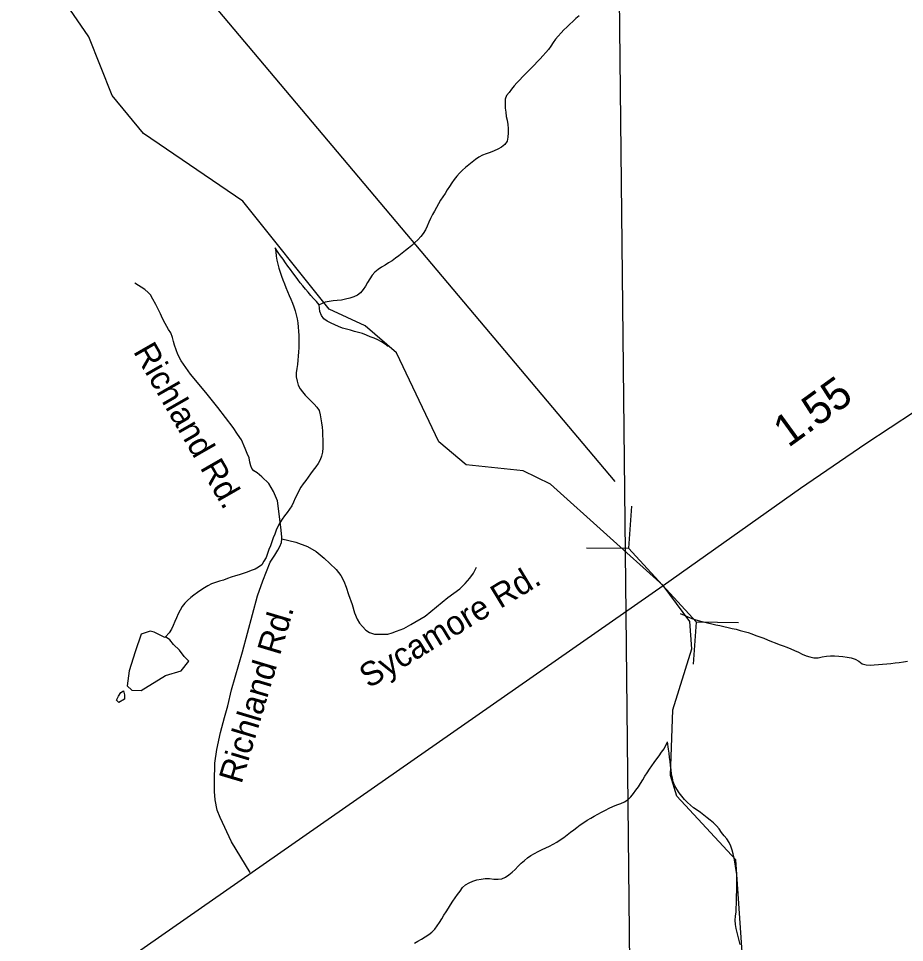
# Model space of a CAD drawing. Extents: x 1950930 to 2061844, y 904556 to 1017002.
# Drawn here: x 1978977 to 1982478, y 957687 to 961340 of the extents above; entities that cross this region are included whole.
import ezdxf

# ---------------------------------------------------------------- set-up
doc = ezdxf.new("R2010")
doc.units = 0
for name, color, linetype in [('Exist Hydrographic Creek Single Shore', 7, 'Continuous'), ('Exist Hydrographic Creek Single Shore Label', 7, 'Continuous'), ('Exist Hydrographic Misc Water Feature', 7, 'Continuous'), ('Exist Road Non-System Type 51', 7, 'Continuous'), ('Exist Road Non-System Type 51 Label', 7, 'Continuous'), ('Exist Road Primary US Attributed', 7, 'Continuous'), ('Exist Road Primary US Mileage Hundredths English Label', 7, 'Continuous'), ('Exist Road Primary US Structure Culvert Number Label', 7, 'Continuous'), ('Exist Utilities Electrical Transmission Line', 7, 'Continuous')]:
    doc.layers.add(name, color=color, linetype=linetype)

msp = doc.modelspace()

# ---------------------------------------------------------------- linework, layer by layer
at = {"layer": 'Exist Hydrographic Creek Single Shore'}
msp.add_lwpolyline([(1981836.5, 957649.2), (1981811.4, 958014.1), (1981578.5, 958265), (1981553.5, 958347.5), (1981562.5, 958606.6), (1981637.6, 958848), (1981629.6, 958956.5), (1981524.5, 959098.7), (1981079.4, 959499.5), (1980971.5, 959551), (1980746.4, 959575.4), (1980638.5, 959666.2), (1980471.4, 960017.5), (1980346.5, 960125.2), (1980204.4, 960190.5), (1979863.4, 960617.6), (1979471.4, 960885), (1979347.5, 961035.2), (1979255.4, 961266.9), (1979180.4, 961376.7)], dxfattribs=at)
at = {"layer": 'Exist Hydrographic Creek Single Shore Label'}
for p, q in [((1981399.4, 959411.5), (1981387.8, 959245.3)), ((1981221.2, 959247.8), (1981387.8, 959245.3)), ((1981656.2, 958953.1), (1981387.8, 959245.3)), ((1981644.6, 958787), (1981656.2, 958953.1)), ((1981822.7, 958950.6), (1981656.2, 958953.1))]:
    msp.add_line(p, q, dxfattribs=at)
at = {"layer": 'Exist Hydrographic Misc Water Feature'}
for points in [[(1981192.7, 961349.7), (1981180, 961339.3), (1981167.5, 961328), (1981155.6, 961316.8), (1981143.7, 961305.6), (1981132.2, 961294.3), (1981120.8, 961282.3), (1981109.9, 961270.1), (1981099.6, 961257.3), (1981090, 961244.4), (1981080.8, 961230.6), (1981071.1, 961216.8), (1981060.7, 961204.7), (1981049.4, 961192.6), (1981038.1, 961180.6), (1981026.8, 961168.5), (1981015.6, 961156.5), (1981004.1, 961144.3), (1980992.4, 961133.1), (1980980.9, 961121), (1980969.2, 961108.9), (1980957.7, 961097), (1980946.7, 961084.9), (1980936, 961072.8), (1980925.3, 961060.7), (1980915.3, 961047.7), (1980905.9, 961034.8), (1980900.7, 961020.2), (1980900.3, 961002.9), (1980900.7, 960985.7), (1980902.2, 960969.3), (1980904.6, 960952.8), (1980907.5, 960937.1), (1980910.6, 960920.6), (1980911.6, 960904.2), (1980911.6, 960887.8), (1980910.8, 960870.6), (1980907.5, 960855.1), (1980899.3, 960841.4), (1980886, 960830.9), (1980871.6, 960823), (1980856.6, 960815.9), (1980841.3, 960810.5), (1980825.7, 960804.2)], [(1980825.7, 960804.2), (1980810.1, 960798.8), (1980795.7, 960791.7), (1980782.4, 960782.2), (1980769.3, 960771.8), (1980756.4, 960761.4), (1980743.7, 960751), (1980731.4, 960739.8), (1980719.9, 960728.5), (1980709.2, 960716.5), (1980699.2, 960703.6), (1980689.5, 960689.7), (1980680.5, 960676), (1980671.5, 960662.2), (1980662.7, 960648.4), (1980653.8, 960634.7), (1980645.2, 960620.9), (1980636.8, 960606.4), (1980628.6, 960592.5), (1980620.4, 960578), (1980612.6, 960564.2), (1980604.6, 960549.6), (1980597.9, 960534.1), (1980592.3, 960518.6), (1980585.8, 960504), (1980576.7, 960490.3), (1980566.5, 960477.3), (1980555.6, 960465.3), (1980543.5, 960454), (1980531.2, 960442.7), (1980518.7, 960432.4), (1980506, 960422), (1980493.1, 960411.6), (1980480.2, 960402), (1980467, 960391.7), (1980453.7, 960382), (1980439.8, 960373.3), (1980425.4, 960364.6), (1980411.3, 960356.6), (1980397.7, 960347.1), (1980385.4, 960336.7), (1980374.6, 960324.6), (1980365.1, 960310.8), (1980356.3, 960296.2), (1980347.9, 960281.7), (1980338.7, 960267.8), (1980328.6, 960255.8), (1980316.5, 960245.4), (1980302, 960239.1), (1980286, 960233.7), (1980269.2, 960229.9), (1980253.2, 960226.2), (1980237, 960224.9), (1980220.4, 960223.5), (1980204.2, 960221.5), (1980188.4, 960217.7), (1980165.4, 960208.4)], [(1979991.5, 960433.4), (1979994, 960417), (1979995.8, 960400.6), (1979998.1, 960384.9), (1980001.4, 960368.4), (1980005.7, 960352.7), (1980011, 960337), (1980016.3, 960321.3), (1980022.3, 960306.5), (1980028, 960290.8), (1980033.8, 960275.8), (1980040.1, 960260.1), (1980046.5, 960245.3), (1980053, 960230.3), (1980059.4, 960214.6), (1980065.1, 960199.7), (1980070.3, 960184), (1980074.6, 960168.4), (1980077.9, 960152.7), (1980080.5, 960136.3), (1980082.2, 960119.8), (1980083.4, 960103.4), (1980084.4, 960087), (1980085, 960070.5), (1980085.2, 960054.1), (1980085, 960037.7), (1980083.8, 960021.4), (1980082.2, 960004.9), (1980080.7, 959988.5), (1980079.1, 959972.1), (1980076.4, 959955.8), (1980074.4, 959939.4), (1980075, 959923), (1980077.9, 959906.5), (1980082.8, 959890.8), (1980090.2, 959876), (1980099.6, 959863.5), (1980110.5, 959851), (1980122.1, 959839.2), (1980134, 959827.4), (1980145.5, 959815.7), (1980156.4, 959803.2), (1980165, 959789.8), (1980169.3, 959773.3), (1980172, 959756.9), (1980174.8, 959741.3), (1980176.7, 959724.7), (1980178.1, 959708.3), (1980178.9, 959691.9), (1980179.4, 959675.5), (1980179.8, 959658.3), (1980179.6, 959641.9), (1980177.9, 959625.5), (1980174.6, 959610), (1980168.9, 959595.4), (1980161.1, 959580.7), (1980151.7, 959567), (1980141.6, 959554), (1980131.4, 959540.3), (1980121.9, 959526.6), (1980112.3, 959513.6), (1980102.3, 959500.7), (1980093, 959487), (1980085, 959473.1), (1980077.7, 959457.8), (1980070.9, 959443.1), (1980064.3, 959428.4), (1980056.7, 959413.9), (1980047.7, 959400.1), (1980038.3, 959386.3), (1980028, 959373.4), (1980018.4, 959360.6), (1980009.4, 959346.7), (1980001.8, 959332.2), (1979995.2, 959316.7), (1979989.7, 959301.2), (1979983.7, 959286.5), (1979978, 959271.1), (1979972.3, 959255.6), (1979966.5, 959240.1), (1979960.8, 959224.6), (1979955.2, 959209.2), (1979947.2, 959194.6), (1979938.4, 959180), (1979926.1, 959170.4), (1979911.8, 959163.3), (1979896.8, 959157.1), (1979881.4, 959151.6), (1979865.6, 959146.2), (1979849.8, 959140.9), (1979834, 959136.2), (1979817.8, 959130.8), (1979802.5, 959126.2), (1979786.9, 959119.9), (1979771.1, 959115.4), (1979755.5, 959110), (1979740.3, 959104.6), (1979725.6, 959096.7), (1979711.6, 959088.7), (1979697.9, 959080)], [(1980165.4, 960208.4), (1980154.5, 960220.9), (1980143.5, 960232.6), (1980132.6, 960245.2), (1980121.7, 960257.6), (1980110.9, 960269.3), (1980100.6, 960282.7), (1980090.4, 960295.2), (1980080.5, 960308.5), (1980070.7, 960321.9), (1980061.2, 960334.4), (1980051.4, 960347.7), (1980041.8, 960361), (1980032.1, 960374.4), (1980022.7, 960387.7), (1980013.1, 960401.8), (1980003.6, 960415.2), (1979991.5, 960433.4)], [(1980438.5, 960042.7), (1980425.6, 960051.9), (1980411.5, 960061.2), (1980397.1, 960068.9), (1980382.2, 960075.8), (1980366.8, 960081.8), (1980351.6, 960087.9), (1980336.2, 960094), (1980320.4, 960098.5), (1980304.6, 960102), (1980288.9, 960107.3), (1980273.3, 960111.8), (1980257.5, 960116.2), (1980241.9, 960122.2), (1980226.7, 960128.3), (1980212, 960135.2), (1980197.4, 960143.7), (1980183.7, 960152.9), (1980174, 960165.5), (1980168.3, 960181.2), (1980165.4, 960208.4)], [(1979697.9, 959080), (1979684.2, 959070.4), (1979670.6, 959060.8), (1979657.9, 959050.4), (1979645.4, 959039.3), (1979634.1, 959028), (1979624.5, 959015.1), (1979616.1, 959000.5), (1979608.5, 958985.8), (1979601.1, 958971.2), (1979594.8, 958955.8), (1979588.8, 958940.2), (1979582.2, 958925.7), (1979572.8, 958911.9), (1979558, 958895.7)], [(1981592.2, 958988.3), (1981607.1, 958981.4), (1981622.1, 958974.6), (1981637.1, 958967.7), (1981652.9, 958963.2), (1981668.4, 958958.8), (1981684.4, 958955.2), (1981700.2, 958950.8), (1981716.4, 958947.2), (1981732.4, 958943.5), (1981748.4, 958939.9), (1981764.4, 958936.3), (1981780.6, 958932.6), (1981796.4, 958929), (1981812.4, 958925.5), (1981828.4, 958921), (1981844.2, 958916.6), (1981859.8, 958912.1), (1981875.1, 958906.9), (1981890.7, 958900.8), (1981905.9, 958894.8), (1981921.5, 958889.6), (1981936.7, 958883.5), (1981952, 958877.5), (1981967.4, 958871.3), (1981982.6, 958865.4), (1981998, 958860.1), (1982013.1, 958854.1), (1982028.5, 958847.9), (1982043.7, 958841.1), (1982058.7, 958834.2), (1982074, 958827.3), (1982089, 958820.5), (1982104.4, 958816.1), (1982120.2, 958812.5), (1982136.2, 958812.9), (1982152.8, 958815.9), (1982169.2, 958818.8), (1982185.6, 958820.2), (1982202, 958820.6), (1982218.4, 958819.4), (1982234.8, 958817.4), (1982251, 958814.6), (1982267.2, 958811.9), (1982283, 958807.4), (1982297.5, 958799.8), (1982311.1, 958788.8), (1982326, 958785.2), (1982342.2, 958784.1), (1982358.2, 958784.6), (1982374.8, 958785.8), (1982391.5, 958787.1), (1982407.9, 958788.4), (1982424.3, 958790.5), (1982440.9, 958792.7), (1982457.3, 958794), (1982473.5, 958796.1), (1982489.7, 958799)], [(1979558, 958895.7), (1979555, 958892.5), (1979513.1, 958914), (1979496.9, 958918.4), (1979461.3, 958906), (1979437.9, 958835.8), (1979414.5, 958761.7), (1979407.1, 958701.2), (1979425.2, 958685.2), (1979461.3, 958683.6), (1979558.7, 958743.2), (1979620.4, 958761.6), (1979649.9, 958799.6), (1979631.9, 958817.2), (1979613.4, 958842.9), (1979589.4, 958864.8), (1979575.1, 958883.1), (1979558, 958895.7)], [(1979373.7, 958635.4), (1979364.7, 958645.5), (1979372.9, 958660.8), (1979381.1, 958675.5), (1979392.4, 958681.7), (1979396.1, 958666.2), (1979396.3, 958648.8), (1979373.7, 958635.4)], [(1980541.5, 957684.2), (1980555.6, 957692), (1980569.8, 957700.8), (1980584.1, 957709.5), (1980598.1, 957718.2), (1980611, 957728.7), (1980621.9, 957739.8), (1980631.9, 957752.8), (1980641.1, 957766.6), (1980649.5, 957780.3), (1980657.9, 957794.9), (1980666.8, 957808.6), (1980675.6, 957822.5), (1980684.4, 957836.2), (1980693.6, 957850), (1980702.6, 957863.8), (1980711.9, 957877.5), (1980721.9, 957890.5), (1980732.2, 957904.1), (1980743.9, 957915.4), (1980757.4, 957923.4), (1980772.8, 957929.6), (1980788.8, 957935.1), (1980805, 957937.9), (1980821.2, 957940.1), (1980838.2, 957939.7), (1980855.4, 957937.7), (1980872.2, 957937.4), (1980887.6, 957939.5), (1980901.8, 957945.7), (1980914.9, 957954.5), (1980927.4, 957965), (1980939.5, 957976.2), (1980951.4, 957988.3), (1980963.7, 958000.3), (1980976, 958011.5), (1980988.5, 958022), (1981002.2, 958031.5), (1981016.2, 958039.4), (1981030.7, 958047.3), (1981045.7, 958054.4), (1981060.7, 958061.5), (1981075.6, 958068.5), (1981090, 958076.4), (1981104.1, 958084.3), (1981117.9, 958093), (1981131.4, 958102.7), (1981144.5, 958112.2), (1981157.7, 958122.7), (1981170.8, 958132.2), (1981183.9, 958141.7), (1981197, 958152.1), (1981210.6, 958161.7), (1981224.1, 958170.5), (1981238, 958179.2), (1981252.4, 958187.2), (1981266.7, 958195.1), (1981281.3, 958203), (1981295.9, 958210), (1981310.6, 958217.9), (1981325.4, 958225), (1981340.8, 958231.2), (1981356.8, 958236.7), (1981371.7, 958243.8), (1981385.7, 958252.5), (1981396.8, 958262.9), (1981407.2, 958275.8), (1981416.8, 958288.8), (1981426.3, 958302.5), (1981434.9, 958316.2), (1981443.5, 958330), (1981452.3, 958344.6), (1981461.1, 958358.4), (1981470.4, 958372.1), (1981479.8, 958385.9), (1981489.4, 958398.9), (1981499.1, 958412.6), (1981508.7, 958425.5), (1981518.1, 958439.3), (1981527.8, 958452.2), (1981541.9, 958479.8)], [(1981828.4, 957678.8), (1981824.1, 957695.3), (1981820.2, 957711), (1981816.3, 957726.6), (1981813, 957743.1), (1981809.9, 957758.8), (1981808.3, 957775.2), (1981810.8, 957791.6), (1981812.4, 957807.9), (1981813, 957824.4), (1981813.6, 957840.7), (1981814, 957857.1), (1981814.6, 957873.5), (1981815.1, 957889.9), (1981815.1, 957906.3), (1981815.3, 957922.7), (1981815.3, 957939.3), (1981815.1, 957955.6), (1981813.4, 957972.1), (1981810.8, 957988.5), (1981807.7, 958004.2), (1981804.4, 958020.7), (1981800.9, 958037.2), (1981796.8, 958052.8), (1981791.7, 958068.4), (1981784.7, 958082.6), (1981775.3, 958096.7), (1981765.2, 958109.2), (1981755.2, 958122.6), (1981745.1, 958135.9), (1981734.7, 958148.4), (1981723, 958160.1), (1981710.7, 958170.2), (1981697.8, 958180.4), (1981684.6, 958190.4), (1981671.7, 958200.6), (1981658.4, 958209.9), (1981644.9, 958220.1), (1981632.4, 958230.1), (1981620.3, 958241), (1981608.6, 958252.8), (1981598.1, 958265.3), (1981587.9, 958278.6), (1981578.6, 958292.8), (1981570.4, 958306.9), (1981564.5, 958321.8), (1981560.8, 958337.5), (1981557.7, 958353.9), (1981555.7, 958369.6), (1981553.8, 958386.9), (1981552, 958403.3), (1981549.5, 958418.9), (1981547.7, 958435.4), (1981545.4, 958451.9), (1981541.9, 958479.8)]]:
    msp.add_lwpolyline(points, dxfattribs=at)
at = {"layer": 'Exist Road Non-System Type 51'}
for points in [[(1980017.5, 959282.4), (1980018.2, 959290.3), (1980014.2, 959329.5), (1980000, 959432.9), (1979985.4, 959469.4), (1979966.8, 959501.9), (1979938.6, 959527.8), (1979920, 959543.8), (1979906.8, 959551.7), (1979898.8, 959561), (1979894.8, 959571.6), (1979890.9, 959586.2), (1979888.1, 959603.4), (1979880.2, 959620.7), (1979872.2, 959639.3), (1979859, 959673.8), (1979843, 959696.3), (1979825.9, 959722.9), (1979765.5, 959802.5), (1979717.6, 959860.9), (1979656.6, 959933.8), (1979619.5, 959986.9), (1979606.2, 960011.9), (1979593.8, 960047.7), (1979589.6, 960063.4), (1979586.2, 960079.2), (1979578.8, 960096.7), (1979569.6, 960110.8), (1979556.4, 960134.1), (1979546.4, 960154), (1979538.1, 960172.3), (1979527.2, 960193.9), (1979519.8, 960208.9), (1979507.4, 960230.5), (1979498.2, 960247.1), (1979489.1, 960257.1), (1979475.8, 960267.9), (1979436.8, 960293.6)], [(1979892.1, 957964), (1979819.1, 958085.6), (1979774.1, 958181.8), (1979762.1, 958210.3), (1979753.9, 958250.8), (1979751.1, 958284.6), (1979751.1, 958323.8), (1979752.5, 958396.1), (1979761.5, 958449.8), (1979776, 958517.4), (1979791.4, 958576.5), (1979804.9, 958622.2), (1979819.5, 958685.9), (1979862.2, 958835.9), (1979921.6, 959057.5), (1979943.2, 959117.2), (1979971.8, 959190.2), (1979990.4, 959218.7), (1980002.2, 959237.9), (1980010.2, 959251.9), (1980016.2, 959267.8), (1980017.5, 959282.4)], [(1980017.5, 959282.4), (1980073.6, 959269.2), (1980118.5, 959252.4), (1980152.8, 959232.6), (1980185.6, 959206.2), (1980207.9, 959185.9), (1980232.4, 959161.9), (1980251, 959137.9), (1980262.4, 959115.1), (1980272, 959092.4), (1980280.6, 959062.4), (1980295, 959023.4), (1980304.6, 958990.5), (1980316, 958965.3), (1980325, 958949.1), (1980336.4, 958936.5), (1980349.6, 958922.1), (1980364.5, 958912.6), (1980383.8, 958905.4), (1980403.2, 958905.4), (1980436.1, 958906.6), (1980454.1, 958911.4), (1980471, 958917.9), (1980499.8, 958928.1), (1980527.9, 958944.3), (1980584.2, 958977.3), (1980673.5, 959051), (1980721.5, 959084.6), (1980741.9, 959106.1), (1980761, 959127.7), (1980775.4, 959146.9), (1980787.5, 959170.2)]]:
    msp.add_lwpolyline(points, dxfattribs=at)
at = {"layer": 'Exist Road Primary US Attributed'}
msp.add_lwpolyline([(1978100.4, 957022.8), (1978444.5, 957098.7), (1978772.5, 957228.5), (1979116.5, 957418.5), (1981524.5, 959098.7), (1982067.5, 959482.7), (1982325.8, 959660.2), (1982518.1, 959785.9), (1982614.1, 959843.7), (1982655.6, 959860.6), (1982718.5, 959898), (1982885.6, 959961), (1983014.4, 959995), (1983195.4, 960020.8), (1983345.5, 960045.9), (1983538, 960068.7), (1983803.4, 960095), (1984009.4, 960120.4), (1984308.8, 960157.5), (1984577.3, 960188.4), (1984884.4, 960234.7), (1985163.6, 960291.1), (1985409.9, 960325.1)], dxfattribs=at)
at = {"layer": 'Exist Road Primary US Structure Culvert Number Label'}
msp.add_line((1981334.3, 959508.8), (1979596.6, 961574.7), dxfattribs=at)
at = {"layer": 'Exist Utilities Electrical Transmission Line'}
for p, q in [((1981377.6, 958984.8), (1981331.3, 963377.3)), ((1981414.6, 955475), (1981377.6, 958984.8))]:
    msp.add_line(p, q, dxfattribs=at)

# ---------------------------------------------------------------- texts
at = {"layer": 'Exist Road Non-System Type 51 Label'}
for s, rotation, p in [('Richland Rd.', 299.8617, (1979428.7, 960023.8)), ('Sycamore Rd.', 31.2303, (1980361.1, 958689.9)), ('Richland Rd.', 73.3427, (1979858.1, 958311))]:
    msp.add_text(s, height=95, rotation=rotation, dxfattribs=at).set_placement(p)
at = {"layer": 'Exist Road Primary US Mileage Hundredths English Label'}
msp.add_text('1.55', height=125, rotation=35.9354, dxfattribs=at).set_placement((1982018.8, 959641.2))

doc.saveas('drawing.dxf')
